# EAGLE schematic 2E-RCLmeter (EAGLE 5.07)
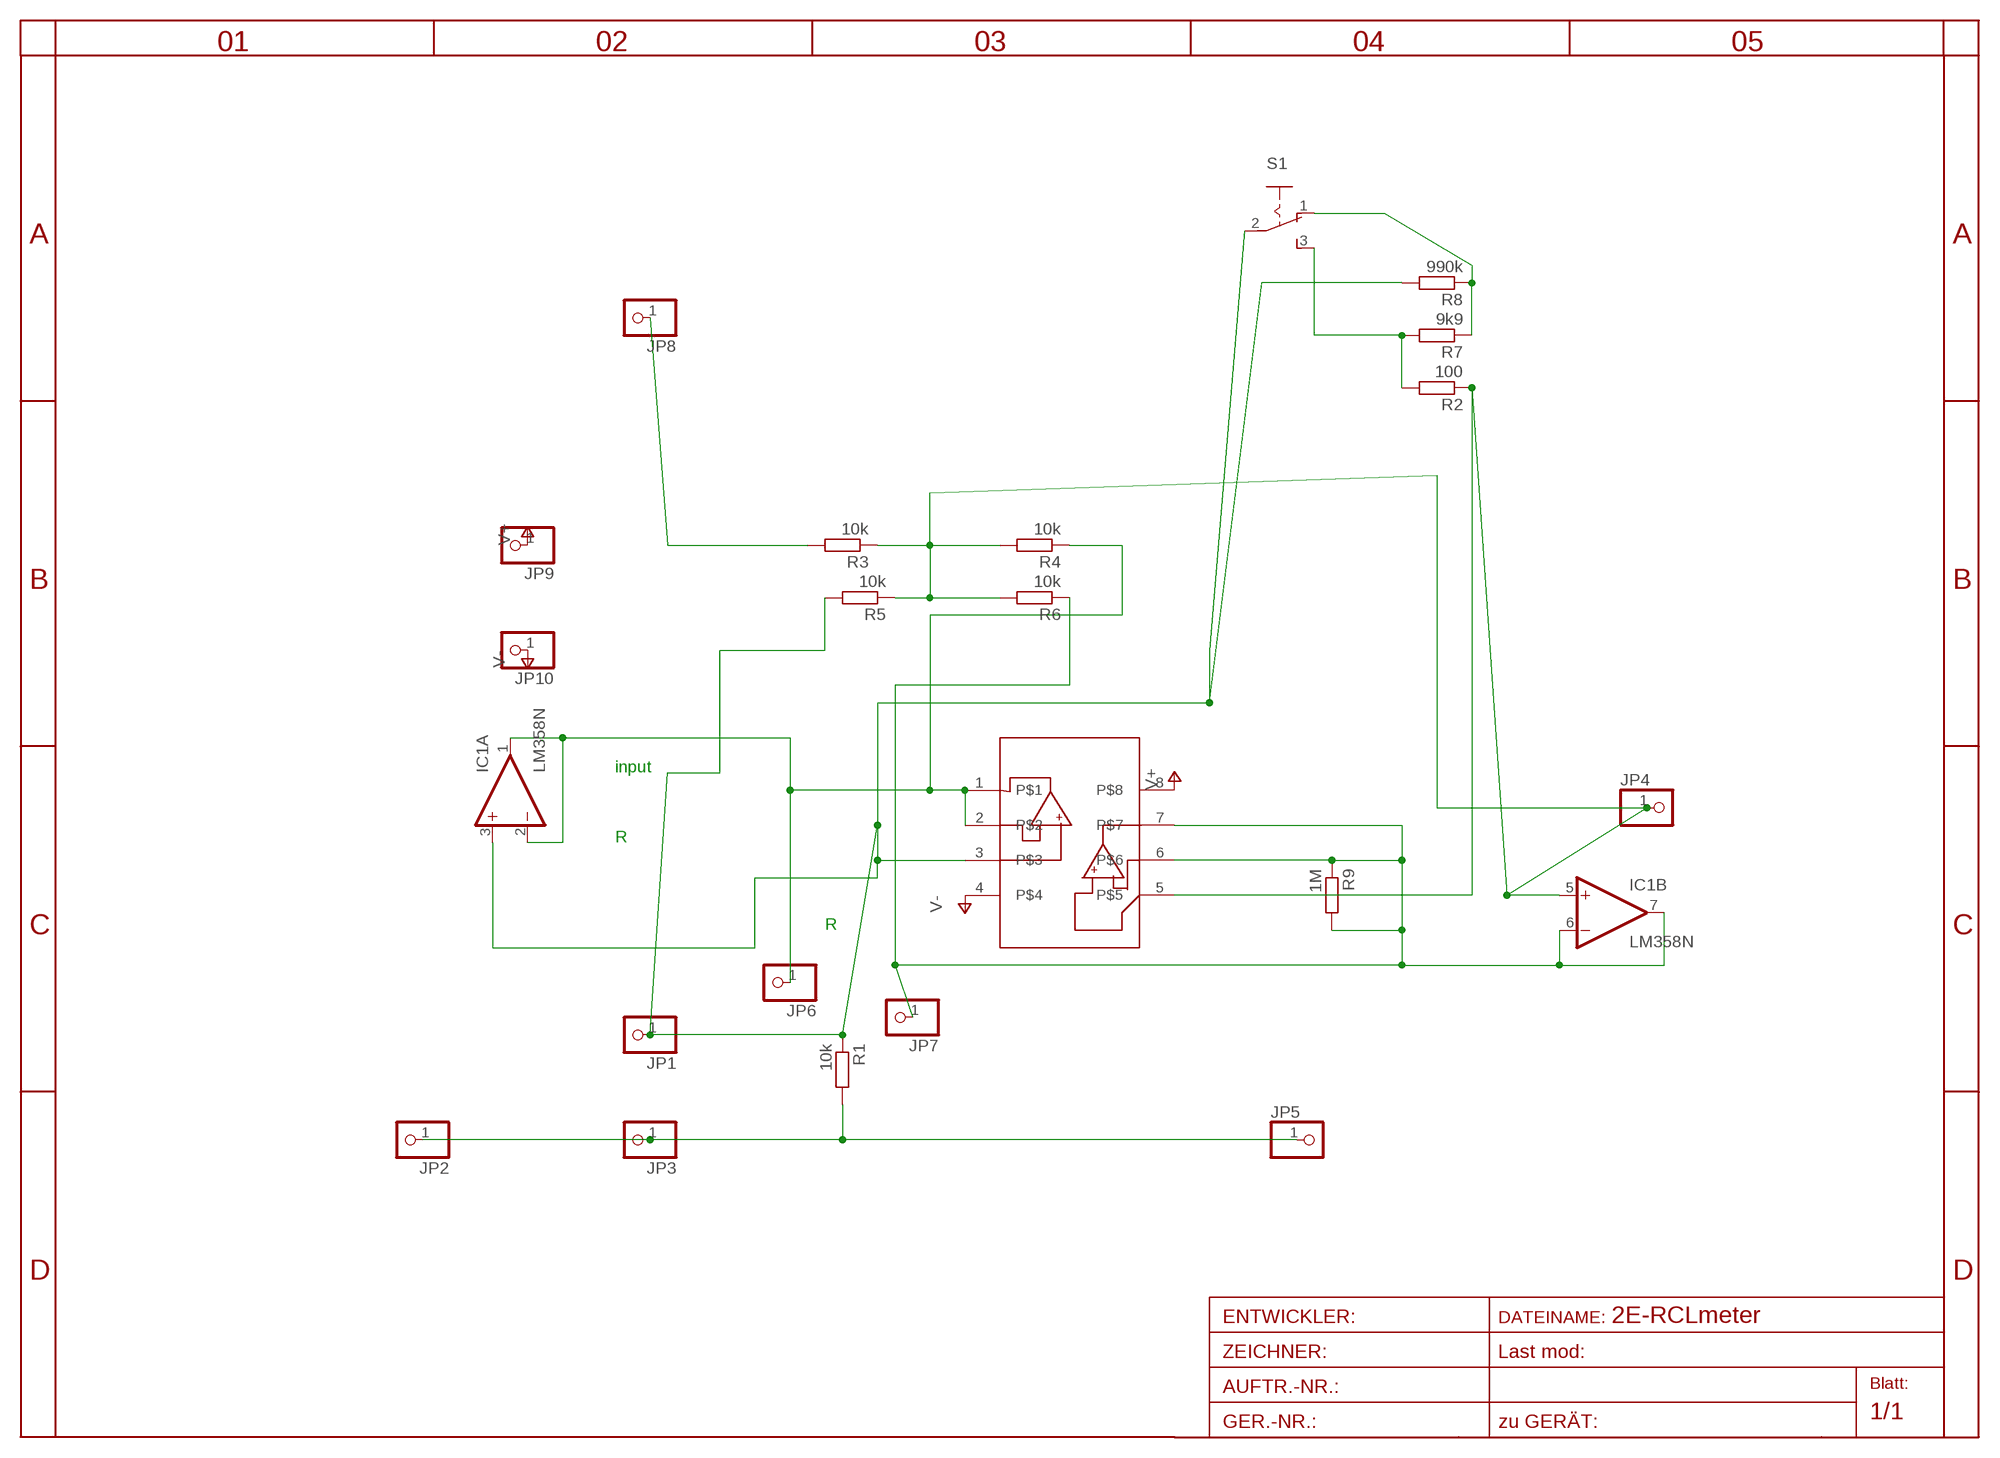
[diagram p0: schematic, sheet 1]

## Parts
IC1  LM358N  [DIL08]
JP1  PINHD-1X1  [1X01]
JP2  PINHD-1X1  [1X01]
JP3  PINHD-1X1  [1X01]
JP4  PINHD-1X1  [1X01]
JP5  PINHD-1X1  [1X01]
JP6  PINHD-1X1  [1X01]
JP7  PINHD-1X1  [1X01]
JP8  PINHD-1X1  [1X01]
JP9  PINHD-1X1  [1X01]
JP10  PINHD-1X1  [1X01]
R1  10k  R-EU_0207/10  [0207/10]
R2  100  R-EU_0207/10  [0207/10]
R3  10k  R-EU_0207/10  [0207/10]
R4  10k  R-EU_0207/10  [0207/10]
R5  10k  R-EU_0207/10  [0207/10]
R6  10k  R-EU_0207/10  [0207/10]
R7  9k9  R-EU_0207/10  [0207/10]
R8  990k  R-EU_0207/10  [0207/10]
R9  1M  R-EU_0204/7  [0204/7]
S1  255SB  [255SB]
U$1  MCP6042SOIC  [SO-08]

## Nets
GND: JP2.1 JP3.1 JP5.1 R1.2
IN_L: JP8.1 R3.2
IN_R: IC1.3(A:+IN) JP1.1 R1.1 R5.2 R8.2 S1.2(P) U$1.3
N$3: R2.2 R7.2 S1.3(S)
N$7: R7.1 R8.1 S1.1(O)
N$8: IC1.5(B:+IN) JP4.1 R2.1 R3.1 R4.2 R5.1 R6.2 U$1.5
OUT_L: IC1.6(B:-IN) IC1.7(B:OUT) JP7.1 R6.1 R9.1 R9.2 U$1.6 U$1.7
OUT_R: IC1.1(A:OUT) IC1.2(A:-IN) JP6.1 R4.1 U$1.1 U$1.2
V+: JP9.1 U$1.8
V-: JP10.1 U$1.4

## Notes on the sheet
- input
- R
- R

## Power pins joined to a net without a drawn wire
V+: IC1.8(P:V+)
V-: IC1.4(P:V-)

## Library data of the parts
IC1 = linear4:LM358: OP AMP
JP1-JP10 = pinhead:PINHD-1X1: PIN HEADER
R1-R9 = rcl-2:R-EU_: RESISTOR, European symbol
S1 = switch:255SB: SLIDING SWITCH distributor Buerklin, 11G810
U$1 = microchip-3:MCP6042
